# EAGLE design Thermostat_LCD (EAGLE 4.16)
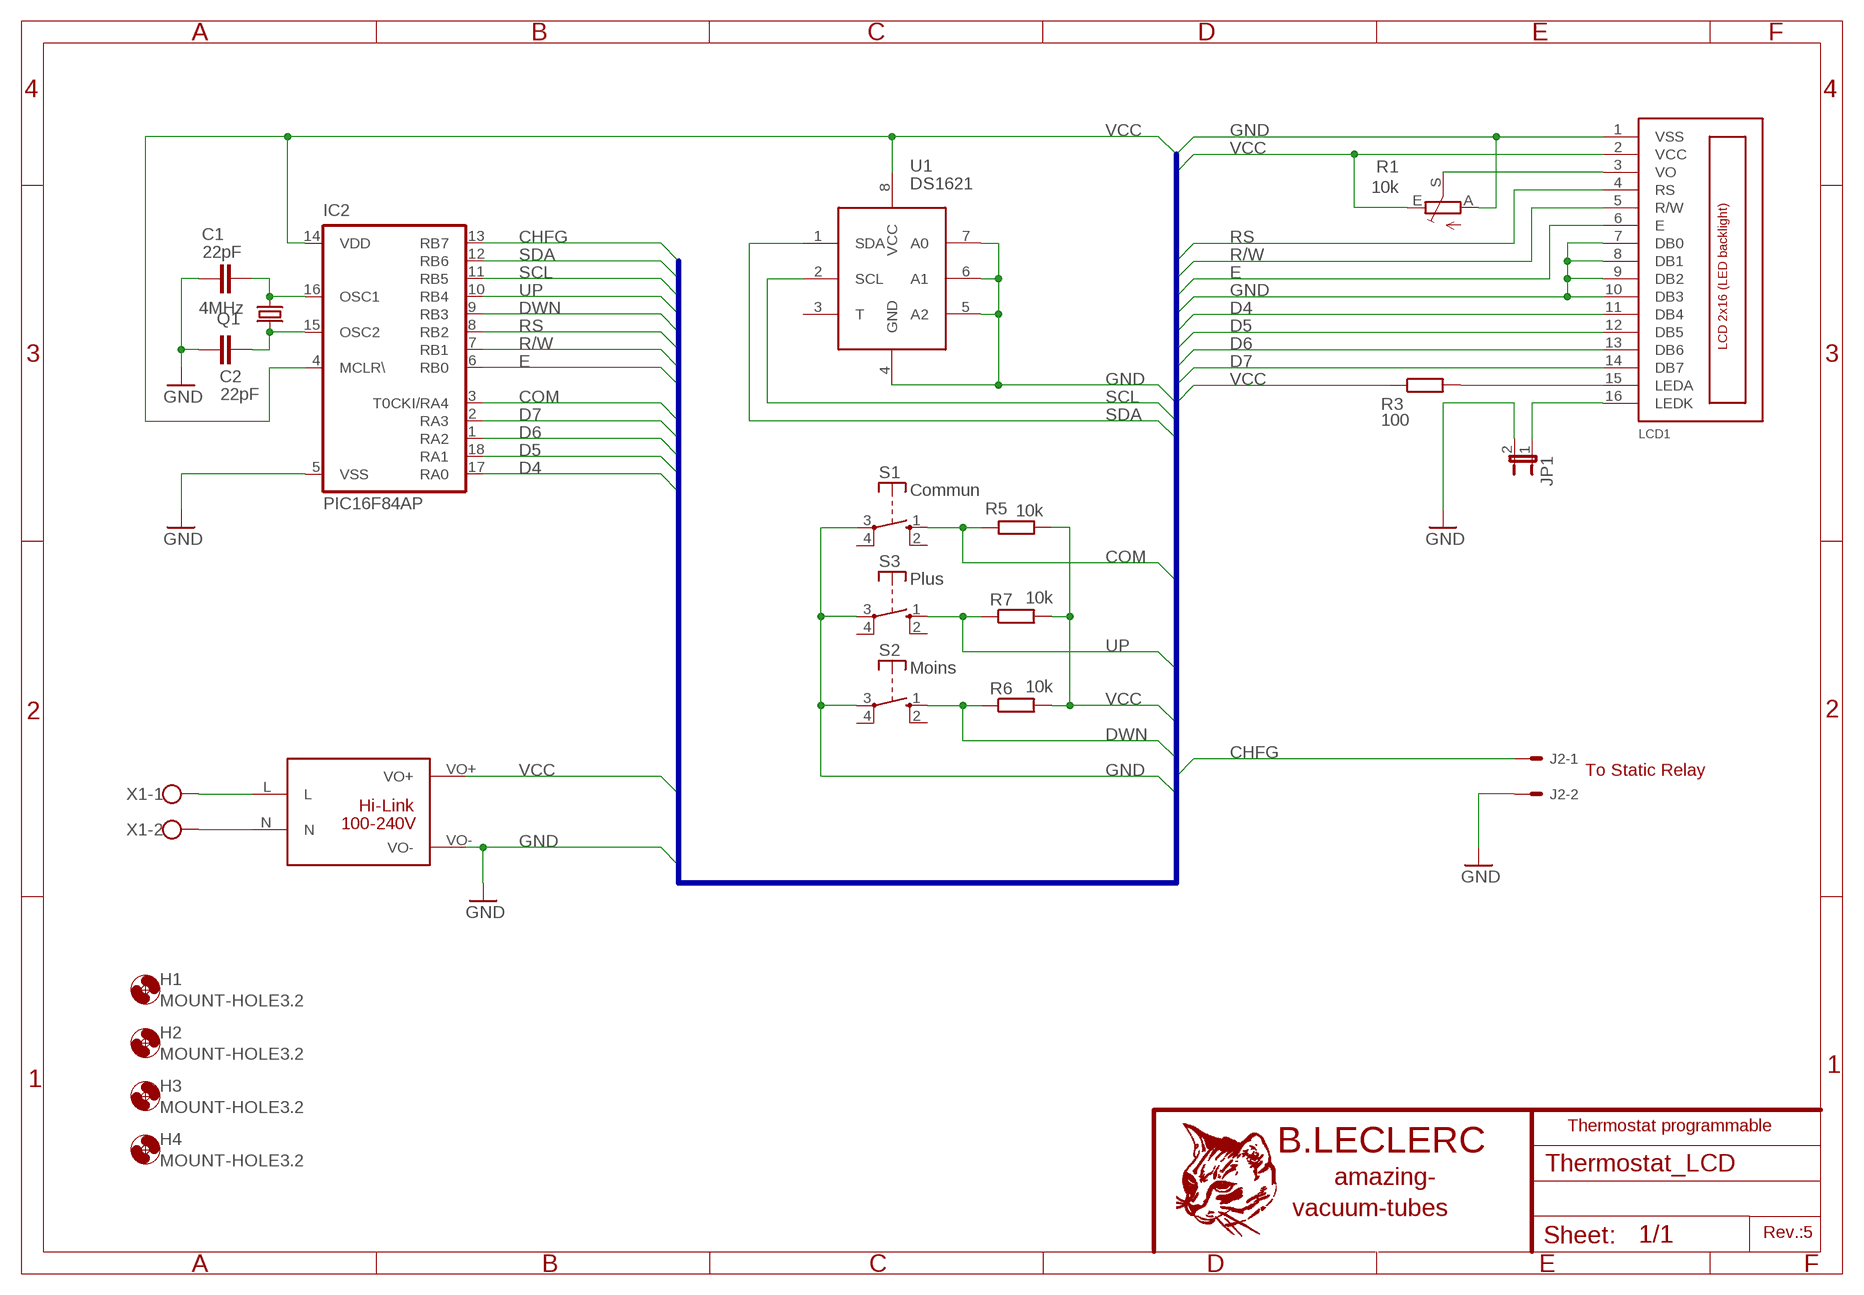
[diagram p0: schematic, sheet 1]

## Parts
C1  22pF  C-EU025-030X050  [C025-030X050]
C2  22pF  C-EU025-030X050  [C025-030X050]
H1  MOUNT-HOLE3.2  [3,2]
H2  MOUNT-HOLE3.2  [3,2]
H3  MOUNT-HOLE3.2  [3,2]
H4  MOUNT-HOLE3.2  [3,2]
IC2  PIC16F84AP  [DIL18]
J2  22-05-7028-02  [7395-02]
JP1  JP1E  [JP1]
LCD1  LCD_2X16_SIL  [HY-1602F]
Q1  4MHz  CRYTALHC49S  [HC49/S]
R1  10k  TRIM_EU-LI10  [LI10]
R3  100  R-EU_0207/12  [0207/12]
R5  10k  R-EU_0207/12  [0207/12]
R6  10k  R-EU_0207/12  [0207/12]
R7  10k  R-EU_0207/12  [0207/12]
S1  Commun  RACON12  [RACON12]
S2  Moins  RACON12  [RACON12]
S3  Plus  RACON12  [RACON12]
U1  DS1621  [DIL08]
U$2  HI-LINKPWRSUP  [HI-LINKPWRSUP]
X1  W237-2N  [W237-2N]

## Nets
CHFG: IC2.13(RB7) J2.1
COM: IC2.3(T0CKI/RA4) R5.2 S1.1(S)
D4: IC2.17(RA0) LCD1.11(DB4)
D5: IC2.18(RA1) LCD1.12(DB5)
D6: IC2.1(RA2) LCD1.13(DB6)
D7: IC2.2(RA3) LCD1.14(DB7)
DWN: IC2.9(RB3) R6.1 S2.1(S)
E: IC2.6(RB0) LCD1.6(E)
GND: C1.1 C2.1 IC2.5(VSS) J2.2 JP1.2 LCD1.1(VSS) LCD1.7(DB0) LCD1.8(DB1) LCD1.9(DB2) LCD1.10(DB3) R1.A S1.3(P) S2.3(P) S3.3(P) U1.4(GND) U1.5(A2) U1.6(A1) U1.7(A0) U$2.VO-
L: U$2.L X1.1
N: U$2.N X1.2
N$1: C1.2 IC2.16(OSC1) Q1.1
N$2: C2.2 IC2.15(OSC2) Q1.2
N$5: LCD1.3(VO) R1.S
N$7: LCD1.15(LEDA) R3.2
N$8: JP1.1 LCD1.16(LEDK)
R/W: IC2.7(RB1) LCD1.5(R/W)
RS: IC2.8(RB2) LCD1.4(RS)
SCL: IC2.11(RB5) U1.2(SCL)
SDA: IC2.12(RB6) U1.1(SDA)
UP: IC2.10(RB4) R7.1 S3.1(S)
VCC: IC2.4(MCLR\) IC2.14(VDD) LCD1.2(VCC) R1.E R3.1 R5.1 R6.2 R7.2 U1.8(VCC) U$2.VO+
Unconnected: S1.2(S) S1.4(P) S2.2(S) S2.4(P) S3.2(S) S3.4(P) U1.3(T)

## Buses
B$1

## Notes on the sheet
- To Static Relay
- Thermostat programmable
- Rev.:5

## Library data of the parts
C1 C2 = rcl:C-EU: CAPACITOR, European symbol
H1-H4 = holes:MOUNT-HOLE: MOUNTING HOLE with drill center marker
IC2 = microchip:PIC16F8*: MICROCONTROLLER 8-Bit PIC16F8X Family - CMOS Flash/EEPROM Pin Compatible : PIC16F83, PIC16CR83, PIC16F84A, PIC16CR84 see also PIC16C*
J2 = con-molex:22-?-02: CONNECTOR
JP1 = jumper:JP1E: JUMPER
LCD1 = lcd_2x16_led_backlight:LCD_2X16_SIL
Q1 = crystal:CRYTAL: CRYSTAL
R1 = pot:TRIM_EU-: POTENTIOMETER
R3 R5-R7 = rcl:R-EU_: RESISTOR, European symbol
S1-S3 = switch-misc:RACON12: ITT SWITCH
U1 = linear:DS1621
U$2 = Arduino:HI-LINKPWRSUP
X1 = con-wago-508:W237-2N: WAGO SREW CLAMP

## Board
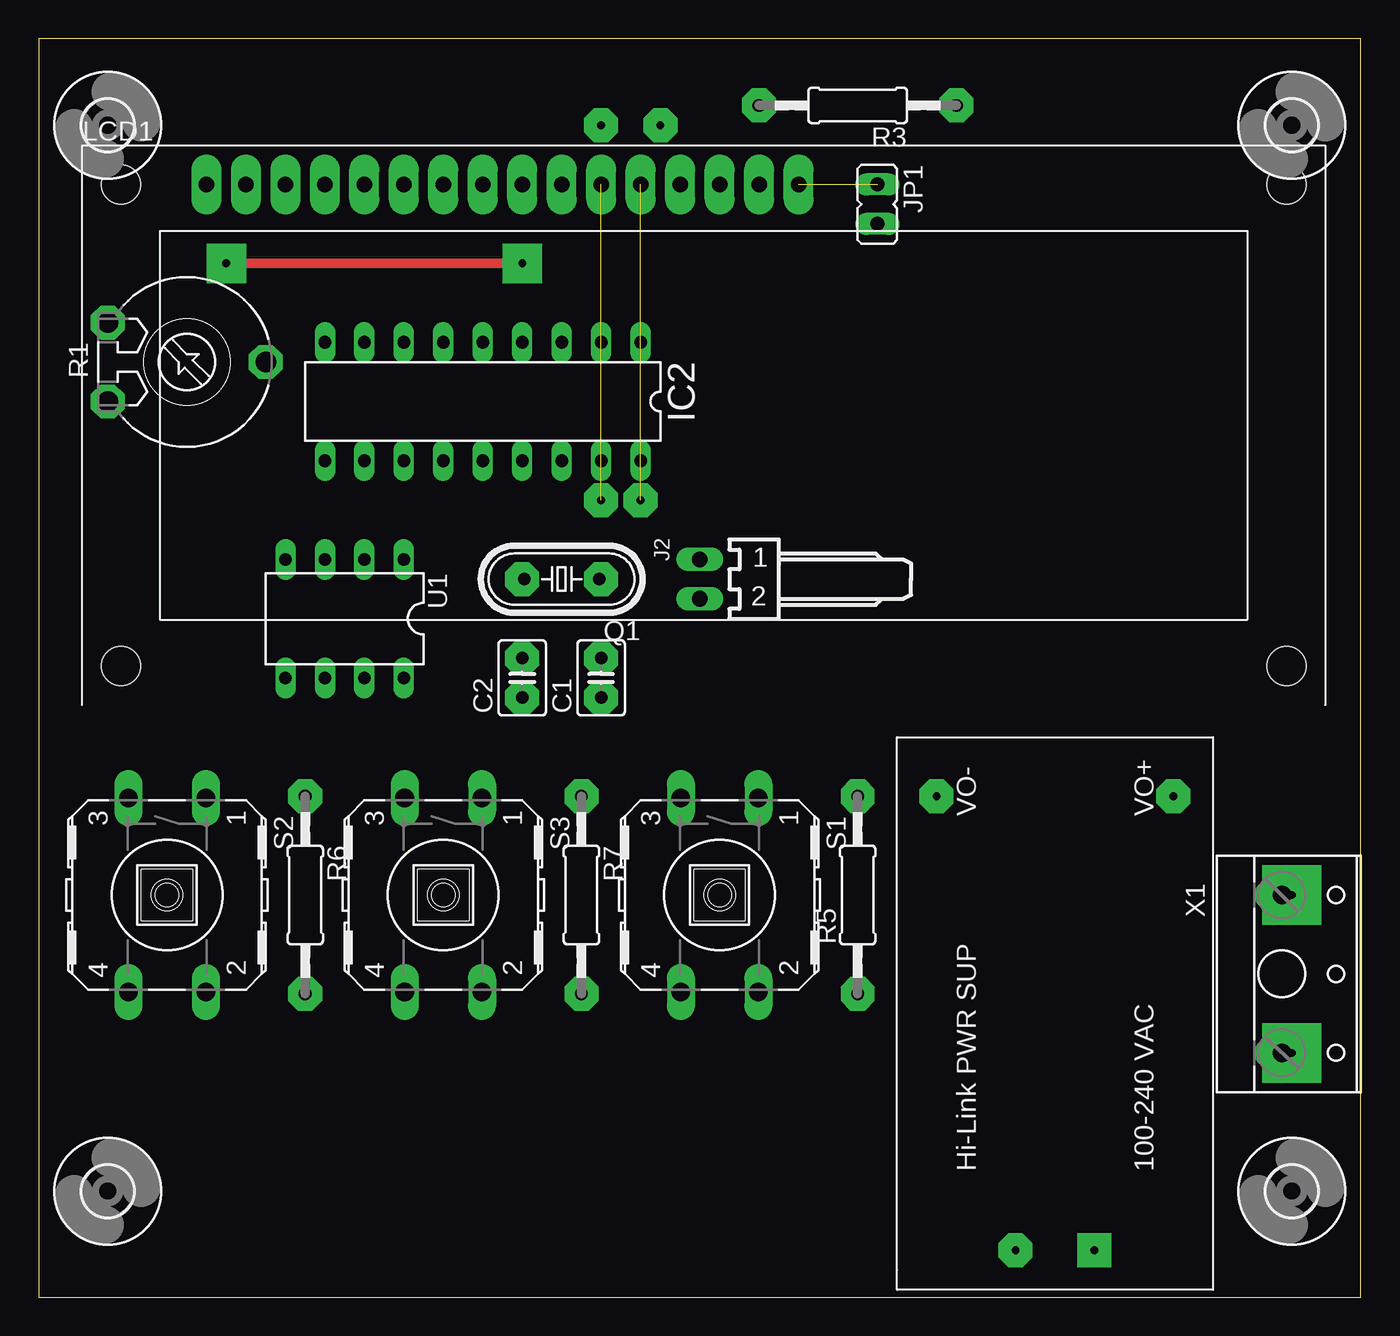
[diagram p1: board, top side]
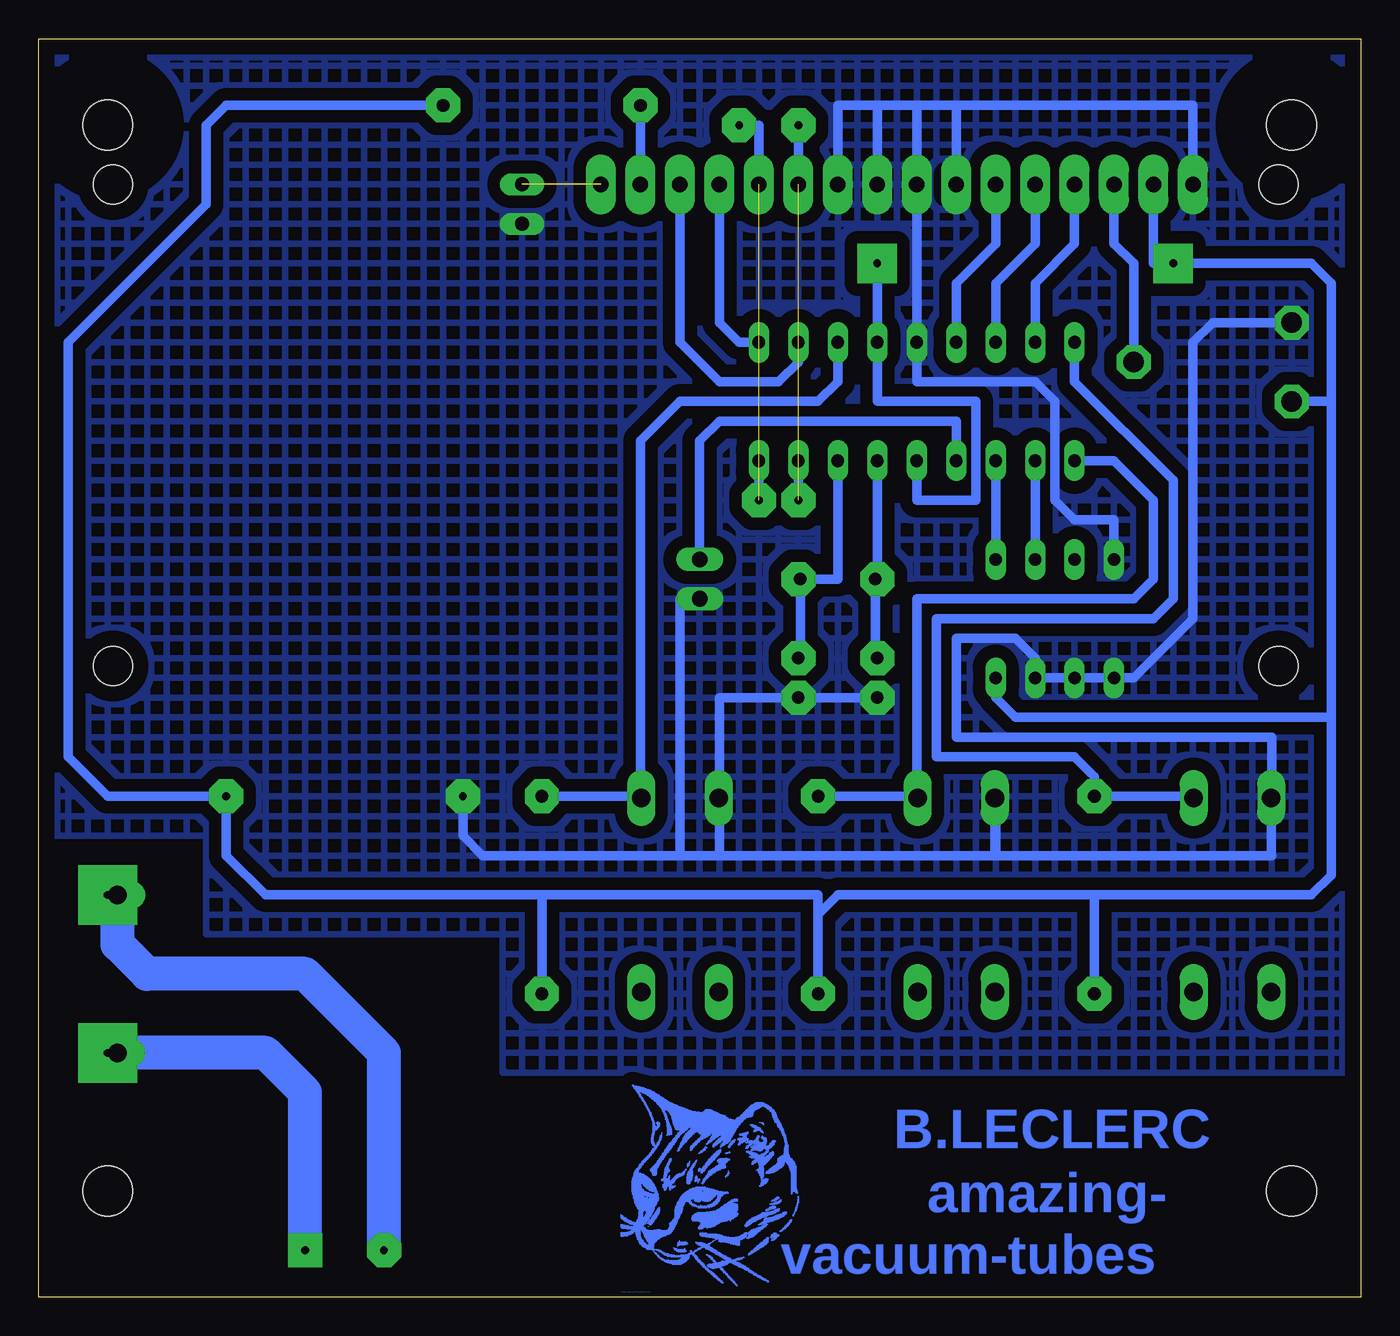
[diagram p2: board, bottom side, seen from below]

Size 85.07 x 80.95 mm. Coordinates in mm from the lower left corner, seen from the top.
Outline: 0,0 85.07,0 85.07,80.95 0,80.95 0,0
Copper layers (1*16): Top 0.035mm / dielectric 1.5mm / Bottom 0.035mm
Design rules "default": minimum track width 10mil, minimum drill 24mil, track to track 8mil, track to pad 8mil, pad to pad 8mil, via to via 8mil, smd to smd 8mil, copper to edge 40mil, drill to drill 8mil, minimum pad ring 10mil, minimum via ring 8mil, stop-mask expansion 4mil, vias tented up to drill 0mil, thermal gap 10mil

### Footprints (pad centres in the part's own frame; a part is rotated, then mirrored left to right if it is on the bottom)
C025-030X050 = drill 0.813 octagon: 1 -1.27,0; 2 1.27,0
3,2 = hole 3.2: 0,0
DIL18 = drill 0.813 long: 1 -10.16,-3.81; 2 -7.62,-3.81; 3 -5.08,-3.81; 4 -2.54,-3.81; 5 0,-3.81; 6 2.54,-3.81; 7 5.08,-3.81; 8 7.62,-3.81; 9 10.16,-3.81; 10 10.16,3.81; 11 7.62,3.81; 12 5.08,3.81; 13 2.54,3.81; 14 0,3.81; 15 -2.54,3.81; 16 -5.08,3.81; 17 -7.62,3.81; 18 -10.16,3.81
7395-02 = drill 1.016 long: 1 1.27,0; 2 -1.27,0
JP1 = drill 0.914 long: 1 0,-1.27; 2 0,1.27
HY-1602F = drill 1 pad 1.93 long: 1 2.54,0; 2 5.08,0; 3 7.62,0; 4 10.16,0; 5 12.7,0; 6 15.24,0; 7 17.78,0; 8 20.32,0; 9 22.86,0; 10 25.4,0; 11 27.94,0; 12 30.48,0; 13 33.02,0; 14 35.56,0; 15 38.1,0; 16 40.64,0 | hole 2.5: -2.96,0; 72.04,0; -2.96,-31; 72.04,-31
HC49/S = drill 0.813 round: 1 -2.413,0; 2 2.413,0
LI10 = drill 1.321 octagon: A -2.54,-5.08; E 2.54,-5.08; S 0,5.08
0207/12 = drill 0.813 octagon: 1 -6.35,0; 2 6.35,0
RACON12 = drill 1.194 long: 1 -6.248,2.489; 2 6.248,2.489; 3 -6.248,-2.489; 4 6.248,-2.489
DIL08 = drill 0.813 long: 1 -3.81,-3.81; 2 -1.27,-3.81; 3 1.27,-3.81; 4 3.81,-3.81; 5 3.81,3.81; 6 1.27,3.81; 7 -1.27,3.81; 8 -3.81,3.81
HI-LINKPWRSUP = drill 0.5 pad 2.184 octagon: L 0,5.08; VO+ 29.21,-5.08; VO- 29.21,10.16 | drill 0.5 pad 2.184 square: N 0,0
W237-2N = drill 1.194 long: 1 -5.08,-0.635; 2 5.08,-0.635

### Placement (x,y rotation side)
C1  36.19,39.84 90 top
C2  31.11,39.84 90 top
H1  80.64,75.4 0 top
H2  4.44,75.4 0 top
H3  80.64,6.82 0 top
H4  4.44,6.82 0 top
IC2  28.57,57.62 180 top
J2  42.54,46.19 90 top
JP1  53.97,70.32 180 top
LCD1  8.25,71.59 0 top
Q1  33.65,46.19 180 top
R1  9.52,60.16 270 top
R3  52.7,76.67 180 top
R5  52.7,25.87 90 top
R6  17.14,25.87 270 top
R7  34.92,25.87 270 top
S1  43.81,25.87 270 top
S2  8.25,25.87 270 top
S3  26.03,25.87 270 top
U1  19.68,43.65 180 top
U$2  67.94,3.01 90 top
U$3  [CHAT1]  47.62,0.47 0 bottom
X1  80.64,20.79 270 top

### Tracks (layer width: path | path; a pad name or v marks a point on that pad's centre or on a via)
CHFG
  Bottom 0.61: IC2.13 26.03,56.35 41.27,56.35 42.54,55.08 J2.1
COM
  Bottom 0.61: IC2.3 33.65,58.89 34.92,57.62 43.81,57.62 46.35,55.08 46.35,32.22 | 46.35,32.22 46.3,32.17 S1.1 | 46.35,32.22 R5.2
D4  (1 unrouted)
  Bottom 0.61: LCD1.11 36.19,75.4 | IC2.17 36.19,51.27
D5  (1 unrouted)
  Bottom 0.61: LCD1.12 38.73,75.4 40,75.4 | IC2.18 38.73,51.27
D6
  Bottom 0.61: LCD1.13 41.27,62.7 40,61.43 IC2.1
D7
  Bottom 0.61: LCD1.14 43.81,61.43 41.27,58.89 37.46,58.89 36.19,60.16 IC2.2
DWN
  Bottom 0.61: IC2.9 18.41,58.89 12.06,52.54 12.06,44.92 13.33,43.65 27.3,43.65 27.3,34.76 18.41,34.76 17.14,33.49 R6.1 10.79,32.22 10.74,32.17 S2.1
E
  Bottom 0.61: IC2.6 26.03,65.24 23.49,67.78 LCD1.6
GND  (via drill 0.5 pad 1.27, 0.5 pad 2.18)
  Bottom 0.61: LCD1.10 33.65,76.67 31.11,76.67 | 28.57,76.67 26.03,76.67 | 28.57,76.67 31.11,76.67 | 31.11,76.67 LCD1.9 | 26.03,76.67 LCD1.7 | 28.57,76.67 LCD1.8 IC2.5 28.57,58.89 20.95,58.89 19.68,57.62 19.68,51.27 18.41,50 15.87,50 U1.4 | U$2.VO- 57.78,29.68 56.51,28.41 43.81,28.41 | 41.27,28.41 43.81,28.41 | 41.27,28.41 v41.27,32.22 | 23.49,28.41 5.71,28.41 5.76,28.46 S2.3 5.71,32.17 5.71,36.03 26.03,36.03 26.03,42.38 22.22,42.38 20.95,41.11 U1.7 U1.6 U1.5 14.6,39.84 10.79,43.65 10.79,61.43 9.52,62.7 R1.A | 23.54,32.17 v23.49,32.22 23.49,28.41 | 23.54,32.17 S3.3 | 23.54,32.17 23.54,28.46 23.49,28.41 | 23.49,28.41 41.27,28.41 | C2.1 C1.1 41.27,38.57 v41.27,32.22 | v41.27,32.22 41.32,32.17 S1.3 | 26.03,76.67 10.79,76.67 LCD1.1 | J2.2 43.81,44.92 43.81,28.41
  other vias: 28.57,61.43 31.11,38.57 36.19,38.57 15.87,47.46 20.95,39.84 18.41,39.84 15.87,39.84 5.71,32.22 4.44,62.7 10.79,71.59 26.03,71.59 28.57,71.59 31.11,71.59 33.65,71.59
  pour Bottom (isolate 0.813, no thermals, hatched): 0.63,80.48 84.45,80.48 84.45,29.68 74.29,29.68 74.29,23.33 55.24,23.33 55.24,14.44 0.63,14.44
L
  Bottom 2.184: X1.1 80,22.7 78.1,20.79 67.94,20.79 62.86,15.71 U$2.L
N
  Bottom 2.184: X1.2 70.48,15.71 67.94,13.17 U$2.N
N$1
  Bottom 0.61: IC2.16 33.65,46.19 Q1.1 | Q1.1 36.19,46.19 | Q1.1 36.06,41.24 C1.2
N$2
  Bottom 0.61: IC2.15 31.11,46.19 Q1.2 31.24,41.24 C2.2
N$5
  Bottom 0.61: LCD1.3 15.87,67.78 14.6,66.51 R1.S
N$7
  Bottom 0.61: LCD1.15 R3.2
N$8  (1 unrouted)
N$12  (via drill 0.5 pad 2.18)
  other vias: 36.19,75.4
N$13  (via drill 0.5 pad 2.18)
  other vias: 40,75.4
N$14  (via drill 0.5 pad 2.18)
  other vias: 38.73,51.27
N$15  (via drill 0.5 pad 2.18)
  other vias: 36.19,51.27
N$16  (via drill 0.5 pad 2.18)
  other vias: 46.35,76.67
N$17  (via drill 0.5 pad 2.18)
  other vias: 59.05,76.67
N$24  (via drill 0.5 pad 2.18)
  other vias: 31.11,46.19
N$25  (via drill 0.5 pad 2.18)
  other vias: 36.19,46.19
N$26  (via drill 0.5 pad 2.18)
  other vias: 31.11,41.11
N$27  (via drill 0.5 pad 2.18)
  other vias: 36.19,41.11
N$28  (via drill 0.5 pad 3.81)
  other vias: 80.64,25.87
N$29  (via drill 0.5 pad 3.81)
  other vias: 80.64,15.71
N$30  (via drill 0.5 pad 2.18)
  other vias: 17.14,32.22
N$31  (via drill 0.5 pad 2.18)
  other vias: 17.14,19.52
N$32  (via drill 0.5 pad 2.18)
  other vias: 34.92,32.22
N$33  (via drill 0.5 pad 2.18)
  other vias: 34.92,19.52
N$34  (via drill 0.5 pad 2.18)
  other vias: 52.7,32.22
N$35  (via drill 0.5 pad 2.18)
  other vias: 52.7,19.52
N$36  (via drill 0.5 pad 1.27)
  other vias: 43.81,71.59
N$37  (via drill 0.5 pad 2.18)
  other vias: 14.6,60.16
N$40  (via drill 0.5 pad 1.27)
  other vias: 28.57,32.22
N$41  (via drill 0.5 pad 1.27)
  other vias: 41.27,71.59
N$42  (via drill 0.5 pad 1.27)
  other vias: 10.79,32.22
N$43  (via drill 0.5 pad 1.27)
  other vias: 38.73,71.59
N$44  (via drill 0.5 pad 1.27)
  other vias: 46.35,32.22
N$45  (via drill 0.5 pad 1.27)
  other vias: 5.71,19.52
N$46  (via drill 0.5 pad 1.27)
  other vias: 10.79,19.52
N$47  (via drill 0.5 pad 1.27)
  other vias: 17.14,19.52
N$48  (via drill 0.5 pad 1.27)
  other vias: 23.49,19.52
N$49  (via drill 0.5 pad 1.27)
  other vias: 28.57,19.52
N$50  (via drill 0.5 pad 1.27)
  other vias: 41.27,19.52
N$51  (via drill 0.5 pad 1.27)
  other vias: 80.64,25.87
N$52  (via drill 0.5 pad 1.27)
  other vias: 80.64,15.71
N$53  (via drill 0.5 pad 1.27)
  other vias: 38.73,53.81
N$54  (via drill 0.5 pad 1.27)
  other vias: 36.19,53.81
N$55  (via drill 0.5 pad 1.27)
  other vias: 33.65,53.81
N$56  (via drill 0.5 pad 1.27)
  other vias: 31.11,53.81
N$57  (via drill 0.5 pad 1.27)
  other vias: 28.57,53.81
N$58  (via drill 0.5 pad 1.27)
  other vias: 26.03,53.81
N$59  (via drill 0.5 pad 1.27)
  other vias: 23.49,53.81
N$60  (via drill 0.5 pad 1.27)
  other vias: 20.95,53.81
N$61  (via drill 0.5 pad 1.27)
  other vias: 18.41,53.81
N$62  (via drill 0.5 pad 1.27)
  other vias: 46.35,19.52
N$63  (via drill 0.5 pad 1.27)
  other vias: 18.41,61.43
N$64  (via drill 0.5 pad 1.27)
  other vias: 20.95,61.43
N$65  (via drill 0.5 pad 1.27)
  other vias: 23.49,61.43
N$66  (via drill 0.5 pad 1.27)
  other vias: 36.19,71.59
N$67  (via drill 0.5 pad 1.27)
  other vias: 31.11,61.43
N$68  (via drill 0.5 pad 1.27)
  other vias: 33.65,61.43
N$69  (via drill 0.5 pad 1.27)
  other vias: 36.19,61.43
N$70  (via drill 0.5 pad 1.27)
  other vias: 38.73,61.43
N$71  (via drill 0.5 pad 1.27)
  other vias: 23.49,39.84
N$75  (via drill 0.5 pad 1.27)
  other vias: 18.41,47.46
N$76  (via drill 0.5 pad 1.27)
  other vias: 23.49,47.46
N$77  (via drill 0.5 pad 1.27)
  other vias: 20.95,47.46
N$78  (via drill 0.5 pad 1.27)
  other vias: 26.03,71.59
N$82  (via drill 0.5 pad 1.27)
  other vias: 20.95,71.59
N$88  (via drill 0.5 pad 1.27)
  other vias: 23.49,71.59
N$89  (via drill 0.5 pad 1.27)
  other vias: 23.49,71.59
N$90  (via drill 0.5 pad 1.27)
  other vias: 18.41,71.59
N$91  (via drill 0.5 pad 1.27)
  other vias: 13.33,71.59
N$92  (via drill 0.5 pad 1.27)
  other vias: 15.87,71.59
N$93  (via drill 0.5 pad 1.27)
  other vias: 46.35,71.59
N$94  (via drill 0.5 pad 1.27)
  other vias: 48.89,71.59
R/W
  Bottom 0.61: LCD1.5 20.95,67.78 23.49,65.24 IC2.7
RS
  Bottom 0.61: IC2.8 20.95,65.24 18.41,67.78 LCD1.4
SCL
  Bottom 0.61: U1.2 IC2.11
SDA
  Bottom 0.61: U1.1 IC2.12
UP
  Bottom 0.61: IC2.10 15.87,53.81 13.33,51.27 13.33,46.19 14.6,44.92 28.57,44.92 28.57,32.22 | 28.57,32.22 28.52,32.17 S3.1 | 28.57,32.22 R7.1
VCC  (via drill 0.5 pad 2.18, 0.5 pad 2.54)
  Top 0.61: v12.06,66.51 v31.11,66.51
  Bottom 0.61: 17.14,25.87 3.17,25.87 1.9,27.14 1.9,37.3 | 17.14,25.87 R6.2 | 17.14,25.87 33.65,25.87 34.92,24.6 R7.2 34.92,25.87 52.7,25.87 | 52.7,25.87 R5.1 | 52.7,25.87 70.48,25.87 73.02,28.41 U$2.VO+ 80.64,32.22 83.18,34.76 83.18,61.43 74.29,70.32 74.29,75.4 73.02,76.67 R3.1 | v31.11,66.51 IC2.4 31.11,57.62 24.76,57.62 24.76,51.27 28.57,51.27 IC2.14 | 13.33,66.51 v12.06,66.51 | U1.8 23.49,38.57 22.22,37.3 1.9,37.3 | 13.33,66.51 LCD1.2 | 13.33,66.51 3.17,66.51 1.9,65.24 1.9,57.62 | 1.9,37.3 1.9,57.62 | 1.9,57.62 R1.E
  other vias: 4.44,57.62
